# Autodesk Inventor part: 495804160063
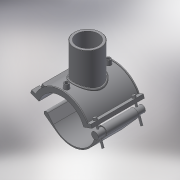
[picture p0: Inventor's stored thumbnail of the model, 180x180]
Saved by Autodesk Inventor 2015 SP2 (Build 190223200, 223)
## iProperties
Created: 2017-07
Part Number: 495804160063
Material: Generic
Description: PLASSON BRANCH SADDLE 160-63
Document SubType Name: Modeling
Designer: KIM
Density: 1 g/cm^3
Appearance: Default
Author: KIM
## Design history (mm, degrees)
derived "495804.ipt"
feature "Solid1::495804.ipt"
feature "Solid2::495804.ipt"
tag "TaggingFeature1"
body "Solid1"
body "Solid2"
other parameters: "d4" = 118, "d5" = 0, "d6" = 0.1, "d8" = 0, "d19" = 6, "d20" = 6, "d21" = 70.8, "d23" = 0, "d24" = 35.4, "d26" = 0, "d27" = 3, "d28" = 3, "d29" = 3, "d30" = 53.33333, "d31" = 6, "d32" = 0, "d33" = 0, "d34" = 0.6, "d40" = 92.56, "d41" = 69.3, "d43" = 0, "d45" = 0, "d47" = 183, "d48" = 63, "d50" = 0, "d70" = 15, "d72" = 0, "d73" = 6, "d75" = 5, "d76" = 0, "d77" = 8, "d79" = 15, "d80" = 47.2, "d82" = 5 deg, "d84" = 4, "d85" = 14, "d86" = 0, "d87" = 3, "d88" = 0, "d89" = 1, "d90" = 1, "d91" = 94.4, "d92" = 0, "d93" = 0.5, "d94" = 84.21053, "d96" = 181.56, "d97" = 2.36, "d98" = 0, "d102" = 1.89, "d103" = 50.4, "d105" = 0, "d109" = -31.33333, "d117" = 0.63, "d120" = 140 deg, "d121" = 24.228, "d122" = 20 deg, "d123" = 356, "d124" = 106.8, "d126" = 0, "d143" = 168, "d150" = 28.8, "d159" = 3.6, "d161" = 4, "d162" = 70.8, "d163" = 0, "d167" = 32, "d168" = 80.90909, "d173" = 1, "d176" = 20 deg, "d177" = 11.2, "d178" = 18, "d180" = 0, "d185" = 38.35, "d186" = 38.35, "d187" = 89, "d188" = 5.4, "d189" = 11.2, "d190" = 0, "d191" = 133.5, "d200" = 9, "d202" = 0, "d216" = 106.2, "d217" = 0, "d221" = 43.66, "d222" = 11.2, "d223" = 6.72, "d225" = 6.72, "d227" = 23.04, "d230" = 99.2, "d236" = 20 deg, "d237" = 96, "d238" = 20 deg, "d239" = 11.2, "H_" = 94, "L_" = 118, "d_t" = 6, "d_1" = 63, "H_1" = 85, "d1" = 178, "d148" = 4, "d160" = 4
